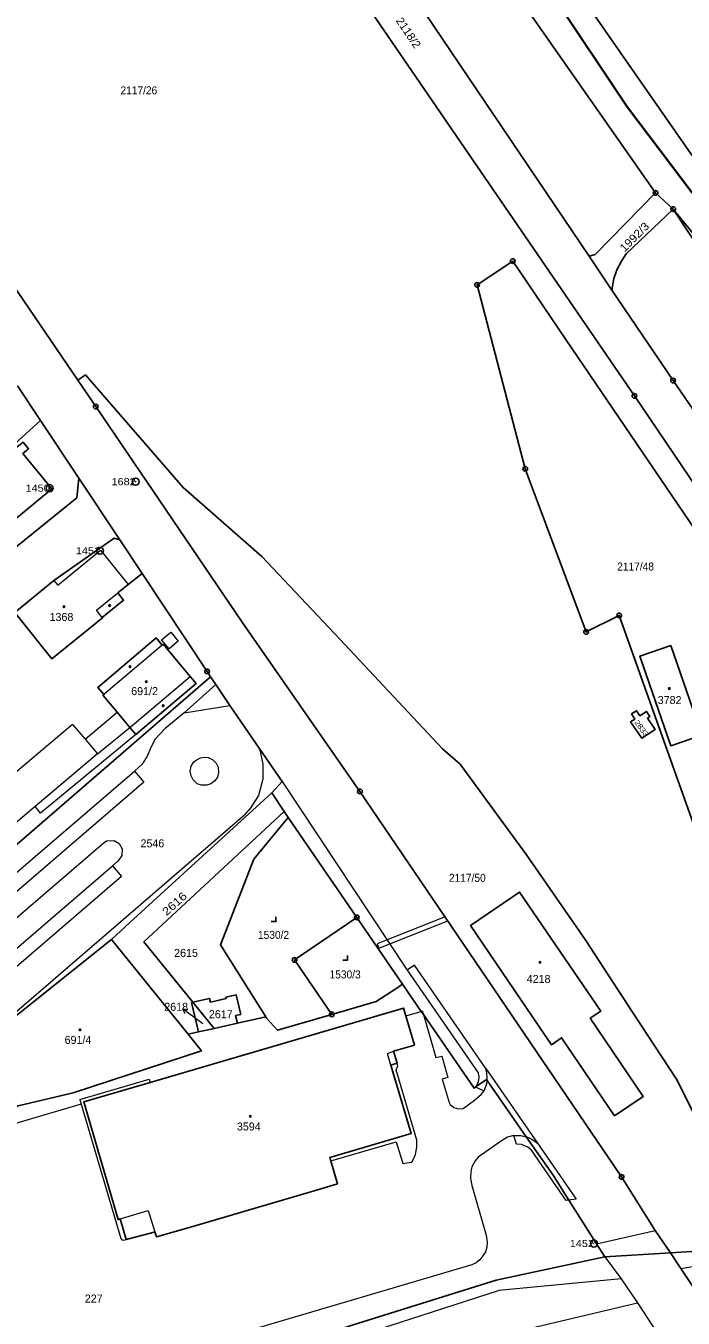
# Model space of a CAD drawing. Extents: x -679733 to -673243, y -1075091 to -1066557.
# Drawn here: x -675992.4 to -675852.7, y -1071520.5 to -1071246 of the extents above; entities that cross this region are included whole.
import ezdxf
from ezdxf.enums import TextEntityAlignment as Align

# ---------------------------------------------------------------- set-up
doc = ezdxf.new("R2010")
doc.units = 0
doc.header["$LTSCALE"] = 0.68
for name, color, linetype, lineweight in [('1', 7, 'Continuous', 25), ('13', 7, 'Continuous', 13), ('3', 7, 'Continuous', 25), ('4', 7, 'Continuous', 13), ('5', 7, 'Continuous', 25), ('6', 7, 'Continuous', 35), ('7', 7, 'Continuous', 13), ('8', 7, 'Continuous', 25)]:
    doc.layers.add(name, color=color, linetype=linetype, lineweight=lineweight)
doc.layers.add('2', color=7, linetype='Continuous')

msp = doc.modelspace()

# ---------------------------------------------------------------- linework, layer by layer
at = {"layer": '1'}
for p, q in [((-676012.95, -1071274.83), (-675981.32, -1071321.28)), ((-675867.83, -1071302.12), (-675872.68, -1071294.91)), ((-675994.12, -1071322.49), (-675989.25, -1071329.82)), ((-675989.25, -1071329.82), (-675981.12, -1071342.08)), ((-675972.41, -1071355.19), (-675981.12, -1071342.08)), ((-675967.67, -1071362.33), (-675972.41, -1071355.19)), ((-675937.44, -1071412.86), (-675940.08, -1071408.93)), ((-675937.44, -1071412.86), (-675936.59, -1071414.13)), ((-675936.59, -1071414.13), (-675922.05, -1071435.37)), ((-675922.05, -1071435.37), (-675912.36, -1071449.53)), ((-675956.86, -1071453.4), (-675952.36, -1071458.95)), ((-675927.57, -1071487.09), (-675926.14, -1071491.98)), ((-675855.42, -1071506.6), (-675869.31, -1071507.45)), ((-675836.69, -1071505.46), (-675855.42, -1071506.6))]:
    msp.add_line(p, q, dxfattribs=at)
for points in [[(-675828.15, -1071376.24), (-675863.07, -1071324.61), (-675918.9, -1071243.14), (-675974.74, -1071161.07), (-676000.25, -1071117.38), (-676033.26, -1071055.17), (-676034.84, -1071052.11), (-676046.89, -1071024.68), (-676041.61, -1071015.35)], [(-675918.01, -1071130.85), (-675918.58, -1071131.4), (-675920.58, -1071133.87), (-675931.7, -1071157.01), (-675894.21, -1071211.19), (-675851, -1071273.28), (-675848.04, -1071276.97), (-675830.99, -1071297.72), (-675807.43, -1071322.9)], [(-675939.18, -1071163.09), (-675890.69, -1071235.61), (-675858.57, -1071281.49), (-675854.82, -1071284.95)], [(-675872.68, -1071294.91), (-675911.27, -1071237.74), (-675947.18, -1071184.19), (-675957.49, -1071168.83)], [(-675858.57, -1071281.49), (-675871.4, -1071294.57), (-675872.68, -1071294.91)], [(-675867.83, -1071302.12), (-675867.44, -1071299.69), (-675866.74, -1071297.7), (-675865.82, -1071295.97), (-675864.8, -1071294.44), (-675854.82, -1071284.95)], [(-675854.82, -1071284.95), (-675848.63, -1071294.37), (-675837.94, -1071309.28), (-675816.23, -1071340.27), (-675801.2, -1071361.46), (-675781.29, -1071388.68)], [(-675854.82, -1071284.95), (-675847.64, -1071293.68), (-675841.21, -1071301.18), (-675834.97, -1071308.68), (-675828.73, -1071315.58), (-675822.64, -1071321.8), (-675814.56, -1071329.82), (-675803.16, -1071340.34), (-675791.31, -1071350.7), (-675764, -1071372.14), (-675760.12, -1071374.06)], [(-675847.63, -1071414.41), (-675850.21, -1071416.33), (-675866.27, -1071371.22), (-675873.33, -1071374.74), (-675886.25, -1071340.1), (-675896.49, -1071301.05), (-675888.9, -1071295.99), (-675877.65, -1071312.62), (-675832.44, -1071379.13), (-675828.15, -1071376.24)], [(-675867.83, -1071302.12), (-675854.84, -1071321.36), (-675808.93, -1071388.15)], [(-675981.32, -1071321.28), (-675979.71, -1071320.17), (-675958.96, -1071344.08), (-675942.19, -1071358.69), (-675925.65, -1071376.26), (-675903.8, -1071399.59), (-675900.1, -1071402.8), (-675886.01, -1071422.07), (-675873.55, -1071440.05), (-675863.47, -1071455.5), (-675854.14, -1071469.73), (-675851.06, -1071475.72), (-675846.24, -1071485.53), (-675836.69, -1071505.46)], [(-675855.42, -1071506.6), (-675858.63, -1071501.84), (-675865.79, -1071490.49), (-675921.38, -1071408.62), (-675946.28, -1071372.89), (-675977.5, -1071326.89), (-675981.32, -1071321.28)], [(-676009.26, -1071336.19), (-676007.17, -1071338.68), (-676004.95, -1071341.45), (-676004.05, -1071342.57), (-676006.86, -1071344.9), (-676000.89, -1071352.08), (-675998.77, -1071350.31), (-675996.85, -1071352.62), (-675986.84, -1071344.35), (-675993.01, -1071336.87), (-675991.76, -1071335.84), (-675992.93, -1071334.41), (-675994.18, -1071335.44), (-675994.71, -1071334.8), (-675989.25, -1071329.82)], [(-675981.12, -1071342.08), (-675981.53, -1071346.24), (-676013.1, -1071371.78), (-676022.08, -1071378.97), (-676031.05, -1071386.16), (-676043.47, -1071395.98), (-676055.74, -1071406.21), (-676068, -1071416.32)], [(-675972.41, -1071355.19), (-675973.57, -1071354.84), (-675986.39, -1071363.8), (-675994.73, -1071370.59)], [(-675994.73, -1071370.59), (-675993.27, -1071372.41), (-675986.84, -1071380.42), (-675976.05, -1071371.76), (-675976.14, -1071371.65), (-675971.58, -1071368), (-675972.81, -1071366.47), (-675970.62, -1071364.7), (-675967.67, -1071362.33)], [(-675967.67, -1071362.33), (-675953.85, -1071383.14), (-675953.13, -1071384.28)], [(-675940.08, -1071408.93), (-675937.88, -1071406.52), (-675942.76, -1071399.41), (-675949.04, -1071390.36), (-675952.01, -1071385.93), (-675953.13, -1071384.28), (-676043.26, -1071462.25)], [(-675974.16, -1071440.07), (-675970.26, -1071436.42), (-675940.08, -1071408.93)], [(-675956.86, -1071453.4), (-675967.28, -1071440.53), (-675937.44, -1071412.86)], [(-675936.59, -1071414.13), (-675943.95, -1071423.01), (-675950.98, -1071441.16), (-675941.39, -1071456.48)], [(-675927.35, -1071455.96), (-675935.25, -1071444.41), (-675922.05, -1071435.37)], [(-675974.16, -1071440.07), (-675984, -1071447.94), (-675992.58, -1071454.77), (-676004, -1071463.72), (-675994.4, -1071475.58)], [(-675994.4, -1071475.58), (-675994.02, -1071475.42), (-675982.33, -1071472.63), (-675955.07, -1071463.71), (-675957.9, -1071460.2), (-675974.16, -1071440.07)], [(-675912.36, -1071449.53), (-675913.76, -1071450.53), (-675917.96, -1071453.21), (-675927.35, -1071455.96)], [(-675869.31, -1071507.45), (-675871.1, -1071504.67), (-675876.97, -1071495.44), (-675880.35, -1071490.11), (-675886.04, -1071481.95), (-675894.36, -1071469.99), (-675894.49, -1071469.8), (-675896.68, -1071471.31), (-675897.13, -1071471.62), (-675907.9, -1071456), (-675908.37, -1071455.32), (-675912.36, -1071449.53)], [(-675955.7, -1071459.7), (-675957.13, -1071453.46), (-675956.86, -1071453.4)], [(-675956.86, -1071453.4), (-675953.31, -1071452.58), (-675953.13, -1071453.36), (-675949.79, -1071452.59), (-675949.85, -1071452.34), (-675947.65, -1071451.83), (-675946.71, -1071455.96), (-675947.81, -1071456.23), (-675947.42, -1071457.84)], [(-675926.14, -1071491.98), (-675929.92, -1071493.07), (-675957.4, -1071501.13), (-675964.63, -1071503.24), (-675964.97, -1071502.15), (-675965.89, -1071502.42), (-675971.03, -1071503.75), (-675972.29, -1071499.42), (-675972.72, -1071499.55), (-675980.07, -1071474.56), (-675965.93, -1071470.41), (-675912.09, -1071454.63), (-675911.6, -1071456.3), (-675909.79, -1071462.5), (-675914.22, -1071463.75), (-675913.44, -1071466.31), (-675914.81, -1071466.73), (-675910.5, -1071481.27), (-675927.79, -1071486.33), (-675927.57, -1071487.09)], [(-675941.39, -1071456.48), (-675947.42, -1071457.84), (-675952.36, -1071458.95), (-675955.7, -1071459.7), (-675957.9, -1071460.2)], [(-675927.35, -1071455.96), (-675938.88, -1071459.34), (-675941.22, -1071456.76), (-675941.39, -1071456.48)], [(-675837.15, -1071533.74), (-675838.99, -1071531.01), (-675840.42, -1071528.88), (-675842.72, -1071525.48), (-675850.05, -1071514.58), (-675853.19, -1071509.92), (-675855.42, -1071506.6)], [(-676016.9, -1071547.75), (-675987.28, -1071541.17), (-675968.47, -1071537.02), (-675954.84, -1071532.51), (-675953.23, -1071531.98), (-675923, -1071521.98), (-675892.45, -1071512.39), (-675869.31, -1071507.45)]]:
    msp.add_lwpolyline(points, dxfattribs=at)
for points in [[(-675972.97, -1071391.79), (-675975.96, -1071388.21), (-675975.76, -1071388.04), (-675977.03, -1071386.54), (-675964.65, -1071376.02), (-675963.38, -1071377.52), (-675963.18, -1071377.36), (-675957.46, -1071384.19), (-675956.18, -1071385.71), (-675969.01, -1071396.53), (-675970.28, -1071395.01)], [(-675855.35, -1071377.62), (-675848.77, -1071396.69), (-675855.29, -1071398.93), (-675861.88, -1071379.88)], [(-675860.31, -1071393.06), (-675858.64, -1071395.46), (-675861.47, -1071397.32), (-675863.87, -1071393.85), (-675862.95, -1071393.24), (-675863.66, -1071392.16), (-675862.6, -1071391.47), (-675861.89, -1071392.54), (-675860.51, -1071391.63), (-675859.77, -1071392.7)], [(-675867.27, -1071477.53), (-675878.53, -1071460.94), (-675880.67, -1071462.45), (-675897.88, -1071437.12), (-675887.45, -1071429.99), (-675870.21, -1071455.3), (-675872.45, -1071456.78), (-675861.21, -1071473.41)]]:
    msp.add_lwpolyline(points, close=True, dxfattribs=at)
at = {"layer": '13'}
msp.add_lwpolyline([(-675917.38, -1071441.88), (-675915.05, -1071440.97), (-675902.71, -1071436.12), (-675903.28, -1071435.27), (-675915.61, -1071440.12), (-675917.74, -1071440.95)], close=True, dxfattribs=at)
at = {"layer": '3'}
for points in [[(-675940.221, -1071436.26), (-675939.22, -1071436.26), (-675939.22, -1071435.26)], [(-675925.001, -1071444.45), (-675924, -1071444.45), (-675924, -1071443.45)]]:
    msp.add_lwpolyline(points, dxfattribs=at)
at = {"layer": '4'}
for p, q in [((-675985.58, -1071364.8), (-675976.48, -1071357.4)), ((-675976.48, -1071357.4), (-675970.62, -1071364.7)), ((-675986.39, -1071363.8), (-675985.58, -1071364.8)), ((-675977.37, -1071370.12), (-675972.81, -1071366.47)), ((-675976.14, -1071371.65), (-675977.37, -1071370.12)), ((-675963.52, -1071376.43), (-675961.57, -1071374.79)), ((-675961.57, -1071374.79), (-675959.97, -1071376.72)), ((-675963.38, -1071377.52), (-675975.76, -1071388.04)), ((-675961.89, -1071378.35), (-675963.52, -1071376.43)), ((-675959.97, -1071376.72), (-675961.89, -1071378.35)), ((-675970.28, -1071395.01), (-675957.46, -1071384.19)), ((-675952.01, -1071385.93), (-675958.73, -1071391.89)), ((-675958.73, -1071391.89), (-675949.04, -1071390.36)), ((-675979.77, -1071397.55), (-675972.97, -1071391.79)), ((-675958.73, -1071391.89), (-675962.82, -1071395.35)), ((-675982.45, -1071394.39), (-676000.4, -1071409.53)), ((-675969.01, -1071396.53), (-675989.24, -1071413.23)), ((-675982.45, -1071394.39), (-675979.77, -1071397.55)), ((-675977.15, -1071400.64), (-675970.28, -1071395.01)), ((-675962.82, -1071395.35), (-675964.87, -1071397.52)), ((-675979.77, -1071397.55), (-675977.15, -1071400.64)), ((-675965.82, -1071399.27), (-675966.55, -1071401.1)), ((-675964.87, -1071397.52), (-675965.82, -1071399.27)), ((-675942.66, -1071399.83), (-675942.76, -1071399.41)), ((-675977.15, -1071400.64), (-675990.4, -1071411.85)), ((-675966.55, -1071401.1), (-675967.61, -1071402.82)), ((-675957.25, -1071403.28), (-675956.74, -1071402.38)), ((-675956.74, -1071402.38), (-675956.18, -1071401.95)), ((-675956.18, -1071401.95), (-675955.22, -1071401.45)), ((-675955.22, -1071401.45), (-675954.47, -1071401.31)), ((-675954.47, -1071401.31), (-675953.62, -1071401.43)), ((-675953.62, -1071401.43), (-675952.67, -1071401.86)), ((-675952.67, -1071401.86), (-675951.91, -1071402.58)), ((-675942.66, -1071399.83), (-675942.01, -1071402.81)), ((-676030.66, -1071456.92), (-675969.27, -1071404.3)), ((-675967.61, -1071402.82), (-675969.27, -1071404.3)), ((-675969.27, -1071404.3), (-675967.26, -1071406.62)), ((-675957.43, -1071404.32), (-675957.25, -1071403.28)), ((-675957.26, -1071405.31), (-675957.43, -1071404.32)), ((-675951.91, -1071402.58), (-675951.5, -1071403.44)), ((-675951.41, -1071404.57), (-675951.67, -1071405.61)), ((-675951.5, -1071403.44), (-675951.41, -1071404.57)), ((-675942.01, -1071402.81), (-675942.03, -1071406.03)), ((-675967.26, -1071406.62), (-676040.66, -1071469.71)), ((-675956.8, -1071406.18), (-675957.26, -1071405.31)), ((-675955.94, -1071406.97), (-675956.8, -1071406.18)), ((-675955.05, -1071407.3), (-675955.94, -1071406.97)), ((-675953.88, -1071407.29), (-675955.05, -1071407.3)), ((-675953.05, -1071407.03), (-675953.88, -1071407.29)), ((-675952.25, -1071406.44), (-675953.05, -1071407.03)), ((-675951.67, -1071405.61), (-675952.25, -1071406.44)), ((-675942.03, -1071406.03), (-675942.96, -1071409.46)), ((-675937.88, -1071406.52), (-675911.33, -1071446.58)), ((-675990.4, -1071411.85), (-675995.06, -1071415.8)), ((-675989.24, -1071413.23), (-675990.4, -1071411.85)), ((-676004.33, -1071463.92), (-675945.87, -1071413.55)), ((-676028.15, -1071464.47), (-675976.1, -1071419.71)), ((-675976.1, -1071419.71), (-675975.21, -1071419.1)), ((-675975.21, -1071419.1), (-675973.61, -1071419.02)), ((-675973.61, -1071419.02), (-675972.52, -1071419.7)), ((-675972.52, -1071419.7), (-675971.91, -1071420.81)), ((-675971.91, -1071420.81), (-675971.98, -1071422.21)), ((-675972.77, -1071423.36), (-675973.96, -1071424.45)), ((-675971.98, -1071422.21), (-675972.77, -1071423.36)), ((-676022.56, -1071466.19), (-675973.96, -1071424.45)), ((-675972.06, -1071426.65), (-676020.59, -1071468.47)), ((-675973.96, -1071424.45), (-675972.06, -1071426.65)), ((-675909.77, -1071445.54), (-675911.33, -1071446.58)), ((-675894.62, -1071467.43), (-675909.77, -1071445.54)), ((-675911.33, -1071446.58), (-675896.27, -1071468.38)), ((-675911.6, -1071456.3), (-675908.37, -1071455.32)), ((-675908.37, -1071455.32), (-675908.12, -1071455.24)), ((-675908.12, -1071455.24), (-675907.9, -1071456)), ((-675907.9, -1071456), (-675905.24, -1071465.14)), ((-675915.55, -1071464.24), (-675914.22, -1071463.75)), ((-675914.81, -1071466.73), (-675915.55, -1071464.24)), ((-675905.24, -1071465.14), (-675904.01, -1071464.81)), ((-675904.01, -1071464.81), (-675902.7, -1071469.4)), ((-675913.71, -1071467.76), (-675913.32, -1071466.89)), ((-675913.32, -1071466.89), (-675913.44, -1071466.31)), ((-675894.62, -1071467.43), (-675883.67, -1071483.31)), ((-675894.4, -1071468.38), (-675894.62, -1071467.43)), ((-675980.9, -1071474.03), (-675966.12, -1071469.75)), ((-675966.12, -1071469.75), (-675965.93, -1071470.41)), ((-675902.7, -1071469.4), (-675903.88, -1071469.76)), ((-675903.88, -1071469.76), (-675902.44, -1071474.66)), ((-675896.27, -1071470.3), (-675896.68, -1071471.31)), ((-675896.27, -1071468.38), (-675896.08, -1071469.32)), ((-675896.08, -1071469.32), (-675896.27, -1071470.3)), ((-675895, -1071472.17), (-675894.45, -1071470.73)), ((-675894.45, -1071470.73), (-675894.36, -1071469.99)), ((-675894.31, -1071469.5), (-675894.4, -1071468.38)), ((-675894.36, -1071469.99), (-675894.31, -1071469.5)), ((-675897.03, -1071474.22), (-675895.62, -1071473.01)), ((-675896.68, -1071471.31), (-675896.73, -1071471.45)), ((-675896.73, -1071471.45), (-675895, -1071472.17)), ((-675895.62, -1071473.01), (-675895, -1071472.17)), ((-675980.59, -1071475.05), (-676020.31, -1071486.63)), ((-675980.9, -1071474.03), (-675980.59, -1071475.05)), ((-675980.59, -1071475.05), (-675972.19, -1071503.6)), ((-675902.44, -1071474.66), (-675902.2, -1071475.13)), ((-675902.2, -1071475.13), (-675901.43, -1071475.75)), ((-675901.43, -1071475.75), (-675900.47, -1071476.02)), ((-675900.47, -1071476.02), (-675899.46, -1071475.92)), ((-675899.46, -1071475.92), (-675897.03, -1071474.22)), ((-675888.65, -1071481.68), (-675889.99, -1071482.07)), ((-675888.13, -1071483.51), (-675888.65, -1071481.68)), ((-675888.65, -1071481.68), (-675887.17, -1071481.71)), ((-675887.17, -1071481.71), (-675886.04, -1071481.95)), ((-675886.04, -1071481.95), (-675885.9, -1071481.98)), ((-675927.57, -1071487.09), (-675913.65, -1071483)), ((-675913.65, -1071483), (-675912.25, -1071487.66)), ((-675909.6, -1071485.71), (-675909.26, -1071484.2)), ((-675891.31, -1071482.85), (-675896.23, -1071486.29)), ((-675889.99, -1071482.07), (-675891.31, -1071482.85)), ((-675887.06, -1071483.6), (-675888.13, -1071483.51)), ((-675885.71, -1071484.16), (-675887.06, -1071483.6)), ((-675885.9, -1071481.98), (-675884.82, -1071482.5)), ((-675884.94, -1071484.79), (-675885.71, -1071484.16)), ((-675884.82, -1071482.5), (-675883.67, -1071483.31)), ((-675883.67, -1071483.31), (-675875.46, -1071495.24)), ((-675912.25, -1071487.66), (-675910.48, -1071487.33)), ((-675910.48, -1071487.33), (-675910.2, -1071487.11)), ((-675910.2, -1071487.11), (-675909.6, -1071485.71)), ((-675896.9, -1071487.04), (-675897.57, -1071488.36)), ((-675896.23, -1071486.29), (-675896.9, -1071487.04)), ((-675877.53, -1071495.51), (-675884.94, -1071484.79)), ((-675897.85, -1071489.35), (-675897.9, -1071490.85)), ((-675897.57, -1071488.36), (-675897.85, -1071489.35)), ((-675897.9, -1071490.85), (-675897.63, -1071492.3)), ((-675897.63, -1071492.3), (-675894.59, -1071502.89)), ((-675876.97, -1071495.44), (-675877.53, -1071495.51)), ((-675875.46, -1071495.24), (-675876.97, -1071495.44)), ((-675972.29, -1071499.42), (-675966.39, -1071497.65)), ((-675966.39, -1071497.65), (-675964.97, -1071502.15)), ((-675972.19, -1071503.6), (-675971.96, -1071503.88)), ((-675971.96, -1071503.88), (-675971.62, -1071503.92)), ((-675971.62, -1071503.92), (-675971.03, -1071503.75)), ((-675894.59, -1071502.89), (-675894.35, -1071504.37)), ((-675871.1, -1071504.67), (-675858.63, -1071501.84)), ((-675894.73, -1071506.38), (-675895.24, -1071507.28)), ((-675894.44, -1071505.4), (-675894.73, -1071506.38)), ((-675894.35, -1071504.37), (-675894.44, -1071505.4)), ((-675853.19, -1071509.92), (-675831.88, -1071506.24)), ((-675897.59, -1071509.15), (-675923.04, -1071516.66)), ((-675896.66, -1071508.7), (-675897.59, -1071509.15)), ((-675895.88, -1071508.07), (-675896.66, -1071508.7)), ((-675895.24, -1071507.28), (-675895.88, -1071508.07)), ((-675869.31, -1071507.45), (-675865.86, -1071512.1)), ((-675865.86, -1071512.1), (-675891.9, -1071514.64)), ((-675865.86, -1071512.1), (-675862.44, -1071517.25)), ((-675892.04, -1071514.69), (-675922.22, -1071524.46)), ((-675891.9, -1071514.64), (-675892.04, -1071514.69)), ((-675923.04, -1071516.66), (-675954.99, -1071526.05)), ((-675889.32, -1071523.57), (-675862.44, -1071517.25)), ((-675862.44, -1071517.25), (-675855.08, -1071528.41))]:
    msp.add_line(p, q, dxfattribs=at)
for points in [[(-675942.96, -1071409.46), (-675944.53, -1071412.06), (-675945.87, -1071413.55)], [(-675909.26, -1071484.2), (-675909.28, -1071482.67), (-675913.71, -1071467.76)]]:
    msp.add_lwpolyline(points, dxfattribs=at)
at = {"layer": '5'}
for centre in [(-675984.2368, -1071369.3892), (-675974.5368, -1071369.1292), (-675970.2368, -1071382.1192), (-675966.7668, -1071385.2892), (-675855.6268, -1071386.7692), (-675963.1668, -1071390.3892), (-675883.1168, -1071444.9192), (-675980.8468, -1071459.2492), (-675944.6568, -1071477.6192)]:
    msp.add_circle(centre, 0.175, dxfattribs=at)
at = {"layer": '6'}
for p, q in [((-675864.57, -1071263.24), (-675880.37, -1071239.53)), ((-675850.79, -1071281.48), (-675864.57, -1071263.24))]:
    msp.add_line(p, q, dxfattribs=at)
at = {"layer": '7'}
msp.add_line((-675959.057, -1071454.754), (-675958.558, -1071455.757), dxfattribs=at)
msp.add_lwpolyline([(-675954.77, -1071457.97), (-675956.66, -1071456.56), (-675959.057, -1071454.754), (-675957.956, -1071454.957)], dxfattribs=at)
at = {"layer": '8'}
for centre, radius in [((-675858.57, -1071281.4899), 0.5), ((-675858.57, -1071281.4899), 0.0303), ((-675854.82, -1071284.9499), 0.5), ((-675854.82, -1071284.9499), 0.0303), ((-675888.9, -1071295.9899), 0.5), ((-675888.9, -1071295.9899), 0.0303), ((-675896.49, -1071301.0499), 0.5), ((-675896.49, -1071301.0499), 0.0303), ((-675854.84, -1071321.3599), 0.5), ((-675854.84, -1071321.3599), 0.0303), ((-675863.07, -1071324.6099), 0.5), ((-675863.07, -1071324.6099), 0.0303), ((-675977.5, -1071326.8899), 0.5), ((-675977.5, -1071326.8899), 0.0303), ((-675886.25, -1071340.0999), 0.5), ((-675886.25, -1071340.0999), 0.0303), ((-675987.28, -1071344.2098), 0.75), ((-675987.28, -1071344.2098), 0.03), ((-675969.02, -1071342.8198), 0.75), ((-675969.02, -1071342.8198), 0.03), ((-675976.6, -1071357.4898), 0.75), ((-675976.6, -1071357.4898), 0.03), ((-675866.27, -1071371.2199), 0.5), ((-675866.27, -1071371.2199), 0.0303), ((-675873.33, -1071374.7399), 0.5), ((-675873.33, -1071374.7399), 0.0303), ((-675953.85, -1071383.1399), 0.5), ((-675953.85, -1071383.1399), 0.0303), ((-675921.38, -1071408.6199), 0.5), ((-675921.38, -1071408.6199), 0.0303), ((-675922.05, -1071435.3699), 0.5), ((-675922.05, -1071435.3699), 0.0303), ((-675935.25, -1071444.4099), 0.5), ((-675935.25, -1071444.4099), 0.0303), ((-675927.35, -1071455.9599), 0.5), ((-675927.35, -1071455.9599), 0.0303), ((-675865.79, -1071490.4899), 0.5), ((-675865.79, -1071490.4899), 0.0303), ((-675871.66, -1071504.6298), 0.75), ((-675871.66, -1071504.6298), 0.03)]:
    msp.add_circle(centre, radius, dxfattribs=at)

# ---------------------------------------------------------------- texts
at = {"layer": '2'}
for s, height, rotation, width, p in [('2118/2', 1.7, 304, 1.05, (-675911.7806, -1071247.9417)), ('1992/3', 1.7, 45, 1.1, (-675862.4675, -1071291.4595)), ('2833', 1.139, 306, 1.15, (-675861.9984, -1071395.5473)), ('2616', 1.7, 42, 1.2, (-675960.2018, -1071433.1001))]:
    msp.add_text(s, height=height, rotation=rotation, dxfattribs=dict(at, width=width)).set_placement(p, align=Align.CENTER)
at = {"layer": '2', "width": 0.95}
msp.add_text('2117/26', height=1.7, dxfattribs=at).set_placement((-675972.25, -1071260.57))
for s, p in [('2117/48', (-675862.81, -1071361.7)), ('2117/50', (-675898.56, -1071427.81)), ('1530/2', (-675939.729, -1071439.93)), ('1530/3', (-675924.519, -1071448.33))]:
    msp.add_text(s, height=1.7, dxfattribs=at).set_placement(p, align=Align.CENTER)
at = {"layer": '2'}
for s, p in [('1368', (-675984.79, -1071372.41)), ('691/2', (-675967.13, -1071388.16)), ('2546', (-675965.47, -1071420.489)), ('2615', (-675958.32, -1071443.759)), ('4218', (-675883.42, -1071449.29)), ('2617', (-675950.94, -1071456.779)), ('691/4', (-675981.28, -1071462.229)), ('3594', (-675944.99, -1071480.62)), ('227', (-675977.929, -1071517.17))]:
    msp.add_text(s, height=1.7, dxfattribs=at).set_placement(p, align=Align.CENTER)
msp.add_text('3782', height=1.7, dxfattribs=at).set_placement((-675858.11, -1071390.06))
msp.add_text('2618', height=1.7, dxfattribs=at).set_placement((-675957.89, -1071455.21), align=Align.RIGHT)
at = {"layer": '8', "width": 1.15}
for s, p in [('1450', (-675987.279, -1071344.96)), ('1682', (-675969.019, -1071343.57)), ('1451', (-675976.599, -1071358.24)), ('1452', (-675871.659, -1071505.379))]:
    msp.add_text(s, height=1.5, dxfattribs=at).set_placement(p, align=Align.RIGHT)

doc.saveas('drawing.dxf')
